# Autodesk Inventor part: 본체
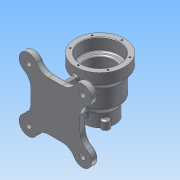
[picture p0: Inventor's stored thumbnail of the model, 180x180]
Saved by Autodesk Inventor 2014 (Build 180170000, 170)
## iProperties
Created: 2017-03
Part Number: 본체
Material: 알루미늄 6061
Document SubType Name: Modeling
Designer: 703
Density: 2.71 g/cm^3
Appearance: 알루미늄 - 평지
Mass: 1000.76 g
Surface Area: 838.864 cm^2
Volume: 369.286 cm^3
Author: 703
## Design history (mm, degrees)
sketch "스케치2" dims "d3" = 140
  geometry: L1 (45, -45)-(-45, -45); L2 (-45, -45)-(-45, 45); L3 (-45, 45)-(45, 45); L4 (45, 45)-(45, -45); L5 (45, -45)-(-45, 45); L6 (-45, -45)-(45, 45); L7 (0, 0)-(49.497, -49.497); L8 (0, 0)-(0, 21.069); L9 (0, 0)-(-23.484, 0); C1 r 17 at (49.497, -49.497); C2 r 17 at (-49.497, -49.497); C3 r 17 at (-49.497, 49.497); C4 r 17 at (49.497, 49.497); 1 further point
  constraints: 18 end point, 4 centre point, 3 parallel, 3 symmetric about line, 2 coincident, 2 midpoint, 2 perpendicular, 1 horizontal, 1 point on line, 6 other
  dimensions: "d1" = 90 distance between parallel lines of L4 L2; "d2" = 90 distance between parallel lines of L3 L1; "d4" = 34 diameter of C1
extrude "돌출1" new body sketch "스케치2" distance "d5" = 12; taper "d6" = 0 deg
fillet "모깎기1" dims "d7" = 25
sketch "스케치3"
  geometry: L1 (-12.842, -45)-(12.842, -45) reference; L2 (0, 0)-(-25, 0); L3 (0, 0)-(25, 0); L4 (-25, 4)-(25, 4); L5 (25, 4)-(25, -4); L6 (25, -4)-(-25, -4); L7 (-25, -4)-(-25, 4); L8 (-25, 4)-(25, -4); L9 (25, 4)-(-25, -4); L10 (0, 0)-(0, 37); L11 (-4, -37)-(4, -37); L12 (4, -37)-(4, 37); L13 (4, 37)-(-4, 37); L14 (-4, 37)-(-4, -37); L15 (-4, -37)-(4, 37); L16 (4, -37)-(-4, 37)
  constraints: 30 end point, 6 parallel, 4 midpoint, 2 horizontal, 2 perpendicular, 1 collinear
  dimensions: "d8" = 25 distance of L2.start L2.end; "d9" = 25 distance of L2.start L3.end; "d10" = 8 distance between parallel lines of L6 L4; "d11" = 50 distance between parallel lines of L7 L5; "d12" = 37 distance of L2.start L10.end; "d13" = 8 distance between parallel lines of L14 L12; "d14" = 74 distance between parallel lines of L11 L13
extrude "돌출2" join sketch "스케치3" distance "d15" = 73; taper "d16" = 0 deg
sketch "스케치4"
  geometry: L1 (0, 73)-(21, 73) reference; L2 (0, 0)-(0, 73) reference; L3 (0, 0)-(12.872, 73); L4 (-9.661, 0)-(-41.497, 0) reference; L5 (12.872, 73)-(0, 73); L6 (0, 0)-(0, 73); 2 further points
  constraints: 6 end point, 1 collinear, 1 parallel, 1 point on line
  dimensions: "d17" = 100 deg angle of L4 L3
extrude "돌출3" cut sketch "스케치4" stored distance "d18" = 73; taper "d19" = 0 deg
node "작업 평면1"
sketch "스케치5"
  geometry: L1 (0, 0)-(0, 82); C1 r 45 at (0, 82)
  constraints: 2 end point, 1 centre point, 1 coincident, 1 vertical
  dimensions: "d21" = 82 distance of L1.start L1.end; "d23" = 90 diameter of C1
extrude "돌출4" join sketch "스케치5" distance "d24" = 20; taper "d25" = 0 deg
sketch "스케치6"
  geometry: L1 (37.178, 30)-(127, 30) reference; L2 (37, 50)-(127, 50) reference; L3 (37.178, 37)-(37.178, 30) reference; L4 (37.178, 37)-(37.178, 37) reference; L5 (37.178, 30)-(37.178, 37) reference; L6 (37.178, 30)-(37.178, 30) reference; L7 (82, 50)-(82, 19); L8 (82, 19)-(118, 19); L9 (118, 19)-(127, 30); L10 (82, 30)-(127, 30); 1 further point
  constraints: 8 end point, 2 parallel, 2 point on line, 1 midpoint, 1 perpendicular
  dimensions: "d26" = 31 distance of L7.start L7.end; "d27" = 36 distance of L7.end L8.end
revolve "회전1" sketch "스케치6" stored, may be unused: angle "d28" = 90 deg
sketch "스케치7"
  geometry: L1 (-4, 3)-(-4, -35.777) reference; L2 (4, 3)-(-4, 3) reference; L3 (4, -35.777)-(4, 3) reference; C1 r 36 at (0, 0); A1 r 36 centre (0, 0) between (4, -35.777) and (-4, -35.777) reference; 1 further point
  constraints: 1 centre point, 1 coincident
  dimensions: "d29" = 72 diameter of C1
extrude "돌출5" join sketch "스케치7" distance "d30" = 34; taper "d31" = 0 deg
sketch "스케치8"
  geometry: L1 (37, 50)-(127, 50) reference; L2 (82, 50)-(82, -15); L3 (82, -15)-(82, -27); L4 (82, -27)-(109.5, -27); L5 (46.223, -15)-(118, -15) reference; L6 (118, 19)-(118, -15) reference; L7 (109.5, -27)-(118, -15); L8 (82, -15)-(118, -15); 1 further point
  constraints: 10 end point, 2 perpendicular, 1 collinear, 1 midpoint
  dimensions: "d32" = 65 distance of L2.start L2.end; "d33" = 12 distance of L2.end L3.end; "d34" = 27.5 distance of L3.end L4.end
revolve "회전2" sketch "스케치8" stored, may be unused: angle "d35" = 90 deg
sketch "스케치9"
  geometry: C1 r 27.5 at (0, 0); A1 r 27.5 centre (0, 0) between (4, -27.208) and (-4, -27.208) reference; 1 further point
  constraints: 1 centre point, 1 coincident
  dimensions: "d36" = 55 diameter of C1
extrude "돌출6" join sketch "스케치9" distance "d37" = 23; taper "d38" = 0 deg
sketch "스케치10"
  geometry: C1 r 45 at (0, 0) reference; C2 r 35 at (0, 0); 1 further point
  constraints: 1 centre point, 1 coincident
  dimensions: "d39" = 70 diameter of C2
extrude "돌출7" cut sketch "스케치10" distance "d40" = 23; taper "d41" = 0 deg
sketch "스케치11"
  geometry: C1 r 35 at (0, 0) reference; C2 r 26 at (0, 0); 1 further point
  constraints: 1 centre point, 1 coincident
  dimensions: "d42" = 52 diameter of C2
extrude "돌출8" cut sketch "스케치11" distance "d43" = 47; taper "d44" = 0 deg
sketch "스케치12"
  geometry: C1 r 26 at (0, 0) reference; C2 r 17.5 at (0, 0); 1 further point
  constraints: 1 centre point, 1 coincident
  dimensions: "d45" = 35 diameter of C2
extrude "돌출9" cut sketch "스케치12" distance "d46" = 30; taper "d47" = 0 deg
sketch "스케치13"
  geometry: L1 (0, 0)-(0, 27.5); C1 r 7 at (0, 27.5); 1 further point
  constraints: 2 end point, 1 centre point, 1 coincident, 1 vertical, 1 vertical alignment, 1 other
  dimensions: "d48" = 14 diameter of C1
extrude "돌출10" join sketch "스케치13" distance "d49" = 15; taper "d50" = 0 deg
sketch "스케치15"
  geometry: A1 r 7 centre (0, 27.5) between (6.943, 26.609) and (-6.943, 26.609) reference; 1 further point
hole "구멍1" sketch "스케치15" at (0, 27.5) diameter "d54" = 3.242; stored, may be unused: countersink angle "d58" = 90 deg, drill point angle "d60" = 118 deg; dims "d55" = 9, "d56" = 4, "d57" = 2, "d59" = 11
sketch "스케치16" dims "d64" = 80
  geometry: L1 (0, 0)-(0, 40); C1 r 45 at (0, 0) reference; 1 further point
  constraints: 2 end point, 1 coincident, 1 vertical, 1 vertical alignment, 2 other
hole "구멍2" sketch "스케치16" at (0, 40) diameter "d65" = 3.242; stored, may be unused: countersink angle "d69" = 90 deg, drill point angle "d71" = 118 deg; dims "d66" = 9, "d67" = 4, "d68" = 2, "d70" = 11
sketch "스케치17"
  geometry: A1 r 17 centre (-49.497, 49.497) between (-34.661, 57.796) and (-57.796, 34.661) reference; 1 further point
hole "구멍3" sketch "스케치17" at (-49.497, 49.497) diameter "d75" = 10; stored, may be unused: countersink angle "d79" = 90 deg, drill point angle "d81" = 118 deg; dims "d76" = 9, "d77" = 4, "d78" = 2, "d80" = 11
chamfer "모따기1" distance "d82" = 1; stored, may be unused: second distance "d83" = 2, angle "d84" = 45 deg
fillet "모깎기2" dims "d85" = 3
fillet "모깎기3" dims "d86" = 3
fillet "모깎기4" dims "d87" = 1
fillet "모깎기5" dims "d91" = 3
fillet "모깎기6" dims "d92" = 3
fillet "모깎기7" dims "d93" = 3
fillet "모깎기8" dims "d94" = 3
node "작업 평면2"
sketch "스케치18"
  geometry: C1 r 5 at (0, -19); 1 further point
  constraints: 1 centre point, 1 coincident
  dimensions: "d95" = 10 diameter of C1
extrude "돌출11" join sketch "스케치18" distance "d97" = 4; taper "d99" = 0 deg; dims "d98" = 1, "d100" = 0
fillet "모깎기9" dims "d101" = 3
sketch "스케치20"
  geometry: C1 r 5 at (0, 0) reference
hole "구멍4" sketch "스케치20" at (0, 0) diameter "d102" = 4.134; stored, may be unused: countersink angle "d106" = 90 deg, drill point angle "d108" = 118 deg; dims "d103" = 9, "d104" = 4, "d105" = 2, "d107" = 21.75
sketch "스케치21"
  geometry: L1 (12.842, 45)-(-12.842, 45) reference; 2 further points
  constraints: 1 other
  dimensions: "d109" = 35 distance of point (35, 0) point (0, 0); "d110" = 45 distance from line of L1 point (35, 0)
extrude "돌출12" join sketch "스케치21" distance "d111" = 0.5; taper "d112" = 0 deg
node "솔리드1"
mirror "대칭1"
pattern_circular "원형 패턴1" dims angle "d52" = 360 deg
pattern_circular "원형 패턴2" dims angle "d62" = 360 deg
pattern_circular "원형 패턴3" dims angle "d73" = 360 deg
mirror "대칭2"
mirror "대칭3"
pattern_circular "원형 패턴4" dims angle "d89" = 360 deg
node "투영된 루프1"
